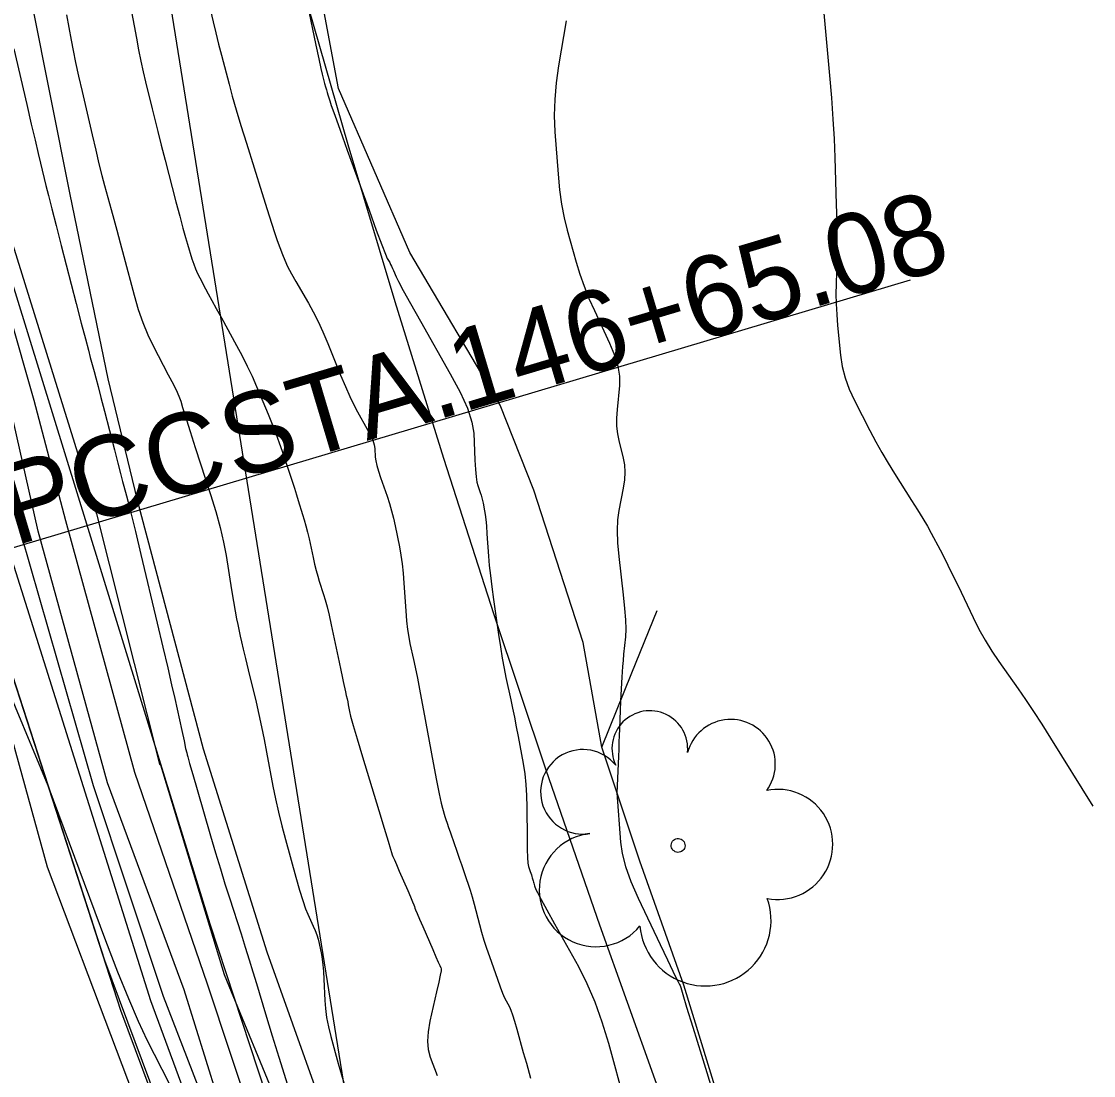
# Model space of a CAD drawing. Extents: x 2030588 to 2035216, y 462285 to 465007.
# Drawn here: x 2031297.82 to 2031335.08, y 464136.2 to 464172.86 of the extents above; entities that cross this region are included whole.
import ezdxf

# ---------------------------------------------------------------- set-up
doc = ezdxf.new("R2010")
doc.units = 0
for name, color, linetype in [('DR_X_Ditch', 7, 'Continuous'), ('DT_P_Pavement_Surface', 7, 'Continuous'), ('DT_X_Contour_Major', 7, 'Continuous'), ('DT_X_Contour_Minor', 7, 'Continuous'), ('GE_X_Alignment', 7, 'Continuous'), ('GE_X_Alignment_100_Cardinal_Points', 7, 'Continuous'), ('MD_P_CONST_LIMITS', 7, 'Continuous'), ('PV_X_EOP', 7, 'Continuous'), ('PV_X_Shoulder_Aggregate', 7, 'Continuous'), ('RW_X_CL', 7, 'Continuous'), ('RW_X_Esmt_SH', 7, 'Continuous'), ('SV_X_Break_Lines', 7, 'Continuous'), ('SV_X_Toe_of_Slope', 7, 'Continuous'), ('SV_X_Top_of_Bank', 7, 'Continuous'), ('UT_X_Electric', 7, 'Continuous'), ('UT_X_Telecom', 7, 'Continuous'), ('VG_X_Cells', 7, 'Continuous')]:
    doc.layers.add(name, color=color, linetype=linetype)

msp = doc.modelspace()

# ---------------------------------------------------------------- linework, layer by layer
at = {"layer": 'DR_X_Ditch'}
msp.add_lwpolyline([(2031320.918, 464098.053), (2031317.245, 464106.191), (2031314.876, 464111.721), (2031311.691, 464118.803), (2031310.107, 464122.659), (2031308.233, 464127.903), (2031305.907, 464134.491), (2031304.283, 464139.376), (2031301.751, 464146.739), (2031299.357, 464155.5), (2031298.256, 464159.683), (2031296.503, 464165.775), (2031294.416, 464172.894)], dxfattribs=at)
at = {"layer": 'DT_P_Pavement_Surface'}
msp.add_lwpolyline([(2031278.406, 464242.26), (2031279.291, 464236.286), (2031282.911, 464211.855), (2031281.24, 464211.467), (2031281.443, 464210.564), (2031286.324, 464189.894), (2031290.945, 464171.988), (2031296.143, 464154.308), (2031300.701, 464140.215), (2031308.554, 464119.142), (2031298.227, 464114.968), (2031289.065, 464111.177), (2031284.681, 464122.798), (2031281.552, 464131.387), (2031280.87, 464133.486), (2031276.172, 464147.96), (2031272.883, 464159.049), (2031266.889, 464182.219), (2031261.238, 464206.822), (2031262.457, 464207.105), (2031257.072, 464231.726), (2031252.323, 464256.477)], dxfattribs=at)
at = {"layer": 'DT_X_Contour_Major'}
for points in [[(2031302.957, 464135.919), (2031302.189, 464137.436), (2031301.883, 464138.079), (2031301.542, 464138.868), (2031301.164, 464139.804), (2031300.751, 464140.887), (2031298.74, 464146.281), (2031296.457, 464151.754), (2031295.994, 464152.828), (2031295.582, 464153.705), (2031295.221, 464154.385), (2031294.911, 464154.867), (2031294.153, 464155.889), (2031293.735, 464156.477), (2031293.049, 464157.475), (2031292.094, 464158.882), (2031290.871, 464160.699), (2031287.253, 464166.089), (2031285.94, 464168.008), (2031284.716, 464169.725), (2031283.581, 464171.239), (2031282.534, 464172.55), (2031277.856, 464178.194)], [(2031316.75, 464172.886), (2031316.481, 464171.315), (2031316.397, 464170.73), (2031316.349, 464170.154), (2031316.336, 464169.587), (2031316.359, 464169.028), (2031316.467, 464167.548), (2031316.517, 464167.011), (2031316.586, 464166.507), (2031316.674, 464166.038), (2031316.782, 464165.603), (2031317.096, 464164.49), (2031317.224, 464164.071), (2031317.372, 464163.651), (2031317.54, 464163.229), (2031317.728, 464162.805), (2031318.258, 464161.673), (2031318.428, 464161.262), (2031318.541, 464160.88), (2031318.597, 464160.525), (2031318.597, 464160.199), (2031318.519, 464159.366), (2031318.5, 464159.064), (2031318.503, 464158.784), (2031318.528, 464158.525), (2031318.575, 464158.287), (2031318.727, 464157.68), (2031318.77, 464157.445), (2031318.784, 464157.192), (2031318.77, 464156.923), (2031318.727, 464156.637), (2031318.575, 464155.853), (2031318.533, 464155.533), (2031318.519, 464155.16), (2031318.534, 464154.736), (2031318.578, 464154.259), (2031318.733, 464152.918), (2031318.781, 464152.45), (2031318.809, 464152.051), (2031318.817, 464151.722), (2031318.805, 464151.462), (2031318.746, 464150.86), (2031318.725, 464150.641), (2031318.708, 464150.434), (2031318.693, 464150.239), (2031318.682, 464150.056), (2031318.637, 464149.231), (2031318.601, 464148.252), (2031318.593, 464148.035), (2031318.584, 464147.803), (2031318.574, 464147.557), (2031318.564, 464147.295), (2031318.511, 464146.04), (2031318.631, 464144.324), (2031318.689, 464143.927), (2031318.813, 464143.469), (2031319.001, 464142.953), (2031319.255, 464142.376), (2031320.019, 464140.759), (2031320.271, 464140.225), (2031320.457, 464139.834), (2031320.576, 464139.586), (2031320.627, 464139.482), (2031320.675, 464139.397), (2031320.691, 464139.365), (2031320.706, 464139.332), (2031320.718, 464139.3), (2031320.728, 464139.268), (2031320.751, 464139.183), (2031320.801, 464139.017), (2031320.934, 464138.584), (2031321.15, 464137.883), (2031321.448, 464136.914), (2031322.353, 464133.973)], [(2031297.556, 464171.913), (2031298.002, 464169.969), (2031298.157, 464169.295), (2031298.288, 464168.73), (2031298.394, 464168.276), (2031298.477, 464167.932), (2031298.665, 464167.161), (2031298.751, 464166.813), (2031298.869, 464166.348), (2031299.018, 464165.767), (2031299.198, 464165.069), (2031299.719, 464163.051), (2031299.896, 464162.367), (2031300.037, 464161.826), (2031300.141, 464161.429), (2031300.209, 464161.176), (2031300.341, 464160.693), (2031300.4, 464160.471), (2031300.48, 464160.168), (2031300.58, 464159.782), (2031300.701, 464159.315), (2031301.049, 464157.961), (2031301.167, 464157.501), (2031301.262, 464157.137), (2031301.332, 464156.869), (2031301.379, 464156.696), (2031301.471, 464156.365), (2031301.528, 464156.144), (2031301.629, 464155.731), (2031301.775, 464155.124), (2031301.966, 464154.326), (2031302.534, 464151.939), (2031302.731, 464151.103), (2031302.899, 464150.388), (2031303.036, 464149.792), (2031303.142, 464149.316), (2031303.386, 464148.206), (2031303.466, 464147.841), (2031303.523, 464147.58), (2031303.558, 464147.423), (2031303.57, 464147.369), (2031303.571, 464147.363), (2031303.593, 464147.285), (2031303.659, 464147.057), (2031303.769, 464146.679), (2031303.923, 464146.149), (2031304.39, 464144.538), (2031304.563, 464143.95), (2031304.729, 464143.396), (2031304.89, 464142.875), (2031305.044, 464142.387), (2031305.447, 464141.132), (2031305.594, 464140.671), (2031305.733, 464140.229), (2031305.863, 464139.807), (2031305.985, 464139.403), (2031306.297, 464138.354), (2031306.414, 464137.965), (2031306.531, 464137.583), (2031306.646, 464137.21), (2031306.762, 464136.845), (2031307.068, 464135.883)]]:
    msp.add_lwpolyline(points, dxfattribs=at)
at = {"layer": 'DT_X_Contour_Minor'}
for points in [[(2031307.541, 464174.495), (2031307.92, 464172.655), (2031308.048, 464172.036), (2031308.149, 464171.558), (2031308.223, 464171.223), (2031308.269, 464171.029), (2031308.354, 464170.703), (2031308.385, 464170.586), (2031308.414, 464170.481), (2031308.441, 464170.389), (2031308.466, 464170.308), (2031308.528, 464170.107), (2031308.584, 464169.944), (2031308.705, 464169.603), (2031308.891, 464169.085), (2031309.141, 464168.39), (2031309.896, 464166.302), (2031310.148, 464165.61), (2031310.338, 464165.099), (2031310.464, 464164.77), (2031310.528, 464164.624), (2031310.616, 464164.474), (2031310.648, 464164.415), (2031310.681, 464164.349), (2031310.715, 464164.276), (2031310.748, 464164.197), (2031310.837, 464163.977), (2031310.915, 464163.82), (2031311.082, 464163.511), (2031311.338, 464163.052), (2031311.683, 464162.441), (2031312.721, 464160.613), (2031313.063, 464159.969), (2031313.313, 464159.409), (2031313.47, 464158.932), (2031313.533, 464158.539), (2031313.579, 464157.602), (2031313.598, 464157.284), (2031313.62, 464157.031), (2031313.646, 464156.843), (2031313.675, 464156.721), (2031313.758, 464156.483), (2031313.788, 464156.393), (2031313.815, 464156.3), (2031313.839, 464156.204), (2031313.861, 464156.106), (2031313.915, 464155.84), (2031313.935, 464155.715), (2031313.955, 464155.542), (2031313.976, 464155.32), (2031313.996, 464155.049), (2031314.05, 464154.261), (2031314.076, 464153.946), (2031314.113, 464153.59), (2031314.162, 464153.195), (2031314.221, 464152.759), (2031314.395, 464151.544), (2031314.46, 464151.109), (2031314.524, 464150.715), (2031314.588, 464150.363), (2031314.651, 464150.051), (2031314.82, 464149.275), (2031314.884, 464148.977), (2031314.947, 464148.663), (2031315.012, 464148.335), (2031315.076, 464147.993), (2031315.25, 464147.059), (2031315.307, 464146.701), (2031315.348, 464146.327), (2031315.374, 464145.938), (2031315.383, 464145.534), (2031315.388, 464144.435), (2031315.393, 464144.066), (2031315.403, 464143.784), (2031315.418, 464143.588), (2031315.439, 464143.478), (2031315.501, 464143.301), (2031315.523, 464143.237), (2031315.542, 464143.18), (2031315.557, 464143.129), (2031315.57, 464143.085), (2031315.599, 464142.975), (2031315.61, 464142.933), (2031315.623, 464142.89), (2031315.638, 464142.845), (2031315.653, 464142.8), (2031315.697, 464142.677), (2031315.75, 464142.567), (2031315.876, 464142.33), (2031316.075, 464141.965), (2031316.348, 464141.474), (2031317.171, 464139.992), (2031317.468, 464139.409), (2031317.741, 464138.769), (2031317.991, 464138.074), (2031318.216, 464137.324), (2031318.787, 464135.248)], [(2031301.609, 464173.378), (2031301.81, 464172.28), (2031301.887, 464171.875), (2031301.966, 464171.487), (2031302.047, 464171.115), (2031302.13, 464170.758), (2031302.355, 464169.828), (2031302.446, 464169.454), (2031302.552, 464169.032), (2031302.672, 464168.561), (2031302.807, 464168.041), (2031303.185, 464166.588), (2031303.317, 464166.088), (2031303.428, 464165.676), (2031303.518, 464165.353), (2031303.587, 464165.119), (2031303.743, 464164.612), (2031303.804, 464164.427), (2031303.87, 464164.254), (2031303.94, 464164.093), (2031304.014, 464163.943), (2031304.218, 464163.559), (2031304.31, 464163.388), (2031304.432, 464163.163), (2031304.584, 464162.885), (2031304.767, 464162.553), (2031305.294, 464161.596), (2031305.486, 464161.237), (2031305.666, 464160.879), (2031305.833, 464160.521), (2031305.989, 464160.163), (2031306.388, 464159.208), (2031306.531, 464158.859), (2031306.66, 464158.527), (2031306.776, 464158.213), (2031306.878, 464157.917), (2031307.132, 464157.15), (2031307.222, 464156.875), (2031307.303, 464156.626), (2031307.375, 464156.404), (2031307.437, 464156.207), (2031307.589, 464155.718), (2031307.646, 464155.527), (2031307.701, 464155.321), (2031307.756, 464155.101), (2031307.81, 464154.866), (2031307.952, 464154.22), (2031308.005, 464153.986), (2031308.059, 464153.771), (2031308.114, 464153.573), (2031308.168, 464153.393), (2031308.315, 464152.938), (2031308.373, 464152.744), (2031308.436, 464152.501), (2031308.505, 464152.211), (2031308.579, 464151.873), (2031308.783, 464150.909), (2031308.854, 464150.575), (2031308.913, 464150.298), (2031308.961, 464150.077), (2031308.997, 464149.913), (2031309.078, 464149.55), (2031309.107, 464149.42), (2031309.132, 464149.301), (2031309.154, 464149.195), (2031309.172, 464149.1), (2031309.216, 464148.863), (2031309.257, 464148.698), (2031309.347, 464148.381), (2031309.485, 464147.91), (2031309.672, 464147.288), (2031310.235, 464145.423), (2031310.421, 464144.808), (2031310.557, 464144.36), (2031310.642, 464144.078), (2031310.678, 464143.964), (2031310.706, 464143.883), (2031310.729, 464143.825), (2031310.777, 464143.711), (2031310.85, 464143.541), (2031310.948, 464143.315), (2031311.243, 464142.638), (2031311.341, 464142.413), (2031311.412, 464142.245), (2031311.457, 464142.136), (2031311.476, 464142.084), (2031311.491, 464142.023), (2031311.512, 464141.965), (2031311.564, 464141.84), (2031311.647, 464141.646), (2031311.762, 464141.383), (2031312.109, 464140.591), (2031312.223, 464140.331), (2031312.304, 464140.145), (2031312.354, 464140.034), (2031312.371, 464139.996), (2031312.373, 464139.995), (2031312.374, 464139.992), (2031312.377, 464139.985), (2031312.381, 464139.974), (2031312.387, 464139.959), (2031312.405, 464139.911), (2031312.4, 464139.848), (2031312.372, 464139.693), (2031312.32, 464139.448), (2031312.245, 464139.111), (2031312.014, 464138.092), (2031311.95, 464137.728), (2031311.93, 464137.398), (2031311.955, 464137.104), (2031312.024, 464136.845), (2031312.269, 464136.2)], [(2031304.386, 464173.244), (2031304.476, 464172.852), (2031304.569, 464172.463), (2031304.665, 464172.077), (2031304.764, 464171.695), (2031305.03, 464170.681), (2031305.142, 464170.268), (2031305.28, 464169.789), (2031305.444, 464169.243), (2031305.632, 464168.631), (2031306.169, 464166.911), (2031306.354, 464166.324), (2031306.505, 464165.851), (2031306.622, 464165.493), (2031306.706, 464165.25), (2031306.885, 464164.755), (2031306.964, 464164.557), (2031307.068, 464164.335), (2031307.197, 464164.089), (2031307.35, 464163.819), (2031307.79, 464163.065), (2031307.956, 464162.766), (2031308.123, 464162.433), (2031308.29, 464162.067), (2031308.459, 464161.668), (2031308.909, 464160.56), (2031309.073, 464160.168), (2031309.226, 464159.825), (2031309.368, 464159.53), (2031309.5, 464159.283), (2031309.837, 464158.689), (2031309.948, 464158.48), (2031310.029, 464158.298), (2031310.08, 464158.144), (2031310.1, 464158.016), (2031310.115, 464157.712), (2031310.131, 464157.582), (2031310.166, 464157.419), (2031310.221, 464157.224), (2031310.296, 464156.997), (2031310.523, 464156.348), (2031310.604, 464156.1), (2031310.678, 464155.846), (2031310.744, 464155.584), (2031310.803, 464155.316), (2031310.951, 464154.589), (2031311.002, 464154.305), (2031311.046, 464154), (2031311.082, 464153.673), (2031311.111, 464153.323), (2031311.177, 464152.362), (2031311.204, 464152.021), (2031311.237, 464151.718), (2031311.276, 464151.453), (2031311.319, 464151.227), (2031311.443, 464150.674), (2031311.499, 464150.407), (2031311.576, 464150.022), (2031311.673, 464149.518), (2031311.789, 464148.896), (2031312.128, 464147.079), (2031312.243, 464146.47), (2031312.334, 464146.004), (2031312.402, 464145.681), (2031312.446, 464145.503), (2031312.532, 464145.217), (2031312.567, 464145.103), (2031312.609, 464144.975), (2031312.657, 464144.832), (2031312.711, 464144.675), (2031312.862, 464144.238), (2031312.92, 464144.072), (2031312.98, 464143.901), (2031313.041, 464143.725), (2031313.105, 464143.544), (2031313.276, 464143.056), (2031313.341, 464142.863), (2031313.408, 464142.649), (2031313.476, 464142.416), (2031313.545, 464142.162), (2031313.732, 464141.458), (2031313.806, 464141.19), (2031313.889, 464140.914), (2031313.98, 464140.631), (2031314.081, 464140.34), (2031314.36, 464139.553), (2031314.457, 464139.285), (2031314.539, 464139.071), (2031314.607, 464138.91), (2031314.659, 464138.803), (2031314.777, 464138.59), (2031314.827, 464138.481), (2031314.886, 464138.317), (2031314.955, 464138.096), (2031315.034, 464137.818), (2031315.258, 464137.004), (2031315.364, 464136.629), (2031315.514, 464136.117)], [(2031299.377, 464173.096), (2031299.538, 464172.217), (2031299.608, 464171.858), (2031299.695, 464171.439), (2031299.799, 464170.962), (2031299.921, 464170.425), (2031300.271, 464168.916), (2031300.396, 464168.382), (2031300.51, 464167.911), (2031300.613, 464167.503), (2031300.704, 464167.158), (2031300.932, 464166.323), (2031301.024, 464165.986), (2031301.127, 464165.6), (2031301.244, 464165.167), (2031301.372, 464164.686), (2031301.73, 464163.339), (2031301.873, 464162.85), (2031302.031, 464162.393), (2031302.204, 464161.969), (2031302.394, 464161.576), (2031302.92, 464160.573), (2031303.095, 464160.234), (2031303.226, 464159.968), (2031303.314, 464159.776), (2031303.357, 464159.658), (2031303.415, 464159.442), (2031303.459, 464159.294), (2031303.547, 464159.013), (2031303.679, 464158.598), (2031303.856, 464158.05), (2031304.385, 464156.411), (2031304.568, 464155.818), (2031304.72, 464155.266), (2031304.839, 464154.756), (2031304.928, 464154.289), (2031305.121, 464153.098), (2031305.189, 464152.687), (2031305.247, 464152.35), (2031305.295, 464152.085), (2031305.333, 464151.893), (2031305.422, 464151.479), (2031305.465, 464151.289), (2031305.524, 464151.033), (2031305.601, 464150.709), (2031305.695, 464150.318), (2031305.968, 464149.185), (2031306.068, 464148.758), (2031306.163, 464148.327), (2031306.253, 464147.891), (2031306.338, 464147.451), (2031306.557, 464146.272), (2031306.646, 464145.824), (2031306.748, 464145.364), (2031306.864, 464144.891), (2031306.993, 464144.407), (2031307.356, 464143.1), (2031307.484, 464142.651), (2031307.595, 464142.287), (2031307.691, 464142.007), (2031307.77, 464141.811), (2031307.96, 464141.4), (2031308.026, 464141.247), (2031308.082, 464141.096), (2031308.127, 464140.947), (2031308.162, 464140.8), (2031308.241, 464140.41), (2031308.268, 464140.247), (2031308.291, 464140.051), (2031308.31, 464139.822), (2031308.324, 464139.56), (2031308.356, 464138.817), (2031308.378, 464138.53), (2031308.422, 464138.224), (2031308.486, 464137.901), (2031308.571, 464137.559), (2031308.825, 464136.625), (2031308.935, 464136.231), (2031309.075, 464135.749)], [(2031325.707, 464173.154), (2031325.9, 464170.989), (2031325.966, 464170.201), (2031326.019, 464169.463), (2031326.058, 464168.775), (2031326.084, 464168.135), (2031326.135, 464166.496), (2031326.15, 464165.917), (2031326.159, 464165.409), (2031326.16, 464164.973), (2031326.154, 464164.608), (2031326.128, 464163.73), (2031326.124, 464163.393), (2031326.132, 464163.041), (2031326.152, 464162.674), (2031326.184, 464162.292), (2031326.283, 464161.252), (2031326.341, 464160.862), (2031326.441, 464160.47), (2031326.582, 464160.078), (2031326.764, 464159.684), (2031327.305, 464158.633), (2031327.51, 464158.245), (2031327.721, 464157.867), (2031327.937, 464157.5), (2031328.158, 464157.144), (2031328.754, 464156.208), (2031328.964, 464155.874), (2031329.148, 464155.573), (2031329.304, 464155.305), (2031329.433, 464155.07), (2031329.743, 464154.489), (2031329.869, 464154.246), (2031330.015, 464153.956), (2031330.181, 464153.618), (2031330.368, 464153.231), (2031330.892, 464152.137), (2031331.096, 464151.733), (2031331.313, 464151.343), (2031331.544, 464150.967), (2031331.788, 464150.605), (2031332.457, 464149.656), (2031332.716, 464149.282), (2031332.991, 464148.87), (2031333.281, 464148.421), (2031333.587, 464147.935), (2031335.051, 464145.577)]]:
    msp.add_lwpolyline(points, dxfattribs=at)
at = {"layer": 'GE_X_Alignment'}
msp.add_ellipse((2031674.732, 464267.126), major_axis=(-271.236, 302.23), ratio=0.999987, start_param=1.129391, end_param=1.463464, dxfattribs=at)
at = {"layer": 'GE_X_Alignment_100_Cardinal_Points'}
msp.add_line((2031285.598, 464151.007), (2031328.715, 464163.873), dxfattribs=at)
at = {"layer": 'MD_P_CONST_LIMITS'}
msp.add_lwpolyline([(2031304.871, 464099.462), (2031318.532, 464105.655), (2031311.904, 464118.546), (2031304.38, 464141.463), (2031297.225, 464164.67), (2031295.574, 464189.665), (2031297.675, 464215.284), (2031293.386, 464239.179), (2031288.691, 464262.969), (2031290.634, 464288.11), (2031294.17, 464303.872), (2031299.488, 464314.858)], dxfattribs=at)
at = {"layer": 'PV_X_EOP'}
msp.add_lwpolyline([(2031353.162, 464035.71), (2031341.874, 464052.676), (2031332.716, 464067.744), (2031330.521, 464071.931), (2031322.023, 464088.196), (2031314.108, 464105.099), (2031307.351, 464122.147), (2031301.267, 464138.466), (2031296.143, 464154.308), (2031290.945, 464171.988), (2031286.324, 464189.894), (2031281.443, 464210.564), (2031280.322, 464215.544), (2031275.666, 464237.435), (2031271.643, 464258.648), (2031268.07, 464277.87), (2031264.482, 464299.113), (2031261, 464318.439), (2031259.92, 464324.373)], dxfattribs=at)
at = {"layer": 'PV_X_Shoulder_Aggregate'}
msp.add_lwpolyline([(2031322.799, 464088.616), (2031315.02, 464105.504), (2031308.326, 464122.489), (2031302.318, 464138.797), (2031297.302, 464154.717), (2031292.39, 464172.399), (2031287.828, 464190.274), (2031283.175, 464210.826), (2031282.124, 464215.96), (2031277.635, 464237.84), (2031273.355, 464258.914)], dxfattribs=at)
at = {"layer": 'RW_X_CL'}
msp.add_ellipse((2031830.081, 464321.523), major_axis=(-382.715, 426.319), ratio=0.999987, start_param=0.998751, end_param=1.776295, dxfattribs=at)
at = {"layer": 'RW_X_Esmt_SH'}
msp.add_lwpolyline([(2031337.215, 464093.874), (2031334.85, 464099.065), (2031332.54, 464104.281), (2031330.285, 464109.521), (2031328.085, 464114.784), (2031325.94, 464120.07), (2031323.851, 464125.378), (2031321.818, 464130.708), (2031319.841, 464136.059), (2031317.921, 464141.431), (2031316.057, 464146.822), (2031314.249, 464152.232), (2031312.499, 464157.662), (2031310.806, 464163.109), (2031309.17, 464168.574), (2031307.591, 464174.056)], dxfattribs=at)
at = {"layer": 'SV_X_Break_Lines'}
msp.add_lwpolyline([(2031279.184, 464230.728), (2031281.431, 464220.57), (2031282.015, 464217.367), (2031283.335, 464211.146), (2031284.794, 464203.774), (2031286.418, 464197.084), (2031288.119, 464190.155), (2031289.378, 464185.603), (2031290.824, 464180.11), (2031293.444, 464172.527), (2031295.235, 464165.396), (2031296.873, 464159.344), (2031297.803, 464155.004), (2031300.31, 464146.294), (2031302.745, 464138.963), (2031304.623, 464134.105), (2031306.989, 464127.43), (2031308.732, 464122.376), (2031310.328, 464118.347), (2031313.222, 464111.465), (2031315.576, 464105.532), (2031318.909, 464097.312)], dxfattribs=at)
at = {"layer": 'SV_X_Toe_of_Slope'}
for points in [[(2031319.938, 464097.809), (2031316.491, 464105.901), (2031313.727, 464111.648), (2031310.928, 464118.563), (2031309.412, 464122.577), (2031307.334, 464127.561), (2031304.997, 464134.269), (2031303.472, 464139.187), (2031300.811, 464146.383), (2031298.392, 464155.139), (2031297.432, 464159.416), (2031295.721, 464165.568), (2031293.774, 464172.608), (2031291.435, 464180.285)], [(2031295.205, 464173.02), (2031297.242, 464165.988), (2031299.111, 464159.952), (2031300.424, 464155.744), (2031302.617, 464147.038), (2031302.647, 464147.006), (2031304.865, 464139.722), (2031306.821, 464134.967), (2031309.208, 464128.22), (2031310.913, 464123.029), (2031312.516, 464119.126), (2031315.85, 464112.157), (2031318.177, 464106.578), (2031321.745, 464098.444)]]:
    msp.add_lwpolyline(points, dxfattribs=at)
at = {"layer": 'SV_X_Top_of_Bank'}
for points in [[(2031317.983, 464147.619), (2031317.338, 464151.26), (2031315.627, 464156.562), (2031314.457, 464159.522), (2031311.314, 464164.823), (2031308.839, 464170.529), (2031307.821, 464175.982), (2031306.821, 464183.989), (2031306.677, 464188.343), (2031307.537, 464194.588)], [(2031298.162, 464173.534), (2031299.494, 464166.843), (2031300.818, 464160.439), (2031301.843, 464156.217), (2031304.128, 464147.57), (2031306.348, 464140.508), (2031308.13, 464135.5), (2031310.623, 464128.848), (2031312.838, 464123.723), (2031313.968, 464120.154), (2031316.941, 464112.78), (2031319.468, 464107.054), (2031322.886, 464098.937), (2031327.538, 464090.525)], [(2031330.924, 464092.363), (2031327.346, 464100.767), (2031325.019, 464109.432), (2031324.794, 464112.72), (2031324.335, 464116.094), (2031323.712, 464119.448), (2031323.358, 464123.84), (2031324.053, 464128.455), (2031323.155, 464131.791), (2031320.835, 464139.352), (2031319.304, 464143.664), (2031317.983, 464147.619), (2031319.031, 464150.204), (2031319.915, 464152.372)]]:
    msp.add_lwpolyline(points, dxfattribs=at)
at = {"layer": 'UT_X_Electric'}
msp.add_lwpolyline([(2031221.843, 464713.466), (2031231.941, 464645.283), (2031244.284, 464562.24), (2031252.852, 464504.34), (2031260, 464456.218), (2031264.868, 464423.288), (2031269.313, 464393.306), (2031274.036, 464361.48), (2031280.969, 464314.78), (2031288.221, 464265.917), (2031292.226, 464240.822), (2031300.292, 464190.304), (2031337.855, 463955.944)], dxfattribs=at)
at = {"layer": 'UT_X_Telecom'}
msp.add_lwpolyline([(2031361.709, 464028.542), (2031356.786, 464035.327), (2031347.681, 464048.933), (2031339.944, 464060.397), (2031329.726, 464073.814), (2031321.673, 464087.15), (2031313.33, 464106.65), (2031305.91, 464124.388), (2031298.718, 464143.455), (2031292.601, 464165.642), (2031287.039, 464187.229), (2031282.348, 464208.081), (2031277.602, 464228.834), (2031275.079, 464242.094), (2031273.133, 464253.288), (2031272.708, 464257.728), (2031274.398, 464259.6), (2031278.694, 464259.868), (2031283.757, 464259.769), (2031285.497, 464261.094)], dxfattribs=at)
at = {"layer": 'VG_X_Cells'}
for centre, major_axis, start_param, end_param in [((2031319.656, 464147.574), (0.879, -0.98), 0.735329, 4.434893), ((2031322.465, 464147.035), (1.037, -1.156), 0.208643, 3.720379), ((2031317.33, 464146.07), (-0.982, 1.095), 4.663255, 8.8604), ((2031324.099, 464144.242), (1.278, -1.426), 5.363032, 8.894083), ((2031317.786, 464142.658), (-1.318, 1.469), 5.65994, 9.576485), ((2031321.586, 464141.601), (1.524, -1.7), 4.06799, 7.462823)]:
    msp.add_ellipse(centre, major_axis=major_axis, ratio=0.999987, start_param=start_param, end_param=end_param, dxfattribs=at)
msp.add_ellipse((2031320.639, 464144.206), major_axis=(-0.16, 0.179), ratio=0.999987, dxfattribs=at)

# ---------------------------------------------------------------- texts
at = {"layer": 'GE_X_Alignment_100_Cardinal_Points'}
for s, p in [('146+65.08', (2031313.168, 464159.272)), (' STA. ', (2031304.236, 464156.607)), ('PCC', (2031297.565, 464154.616))]:
    msp.add_text(s, height=2.7997, rotation=16.6154, dxfattribs=at).set_placement(p)

doc.saveas('drawing.dxf')
